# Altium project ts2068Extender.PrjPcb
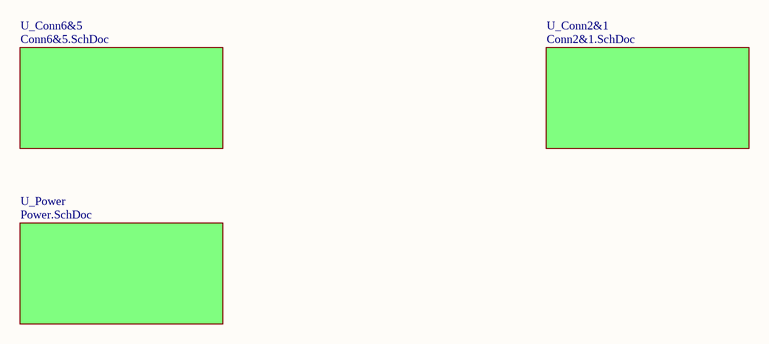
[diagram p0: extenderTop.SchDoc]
4 sheets, 15 parts. Net scope: global (net labels, ports and power ports of the same name join across sheets).
Sheets:
  extenderTop.SchDoc
    U_Power = Power.SchDoc
    U_Conn6&5 = Conn6&5.SchDoc
    U_Conn2&1 = Conn2&1.SchDoc

## Sheet extenderTop.SchDoc
size A

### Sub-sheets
U_Conn2&1 = Conn2&1.SchDoc: no entries
U_Conn6&5 = Conn6&5.SchDoc: no entries
U_Power = Power.SchDoc: no entries

## Sheet Power.SchDoc
size A
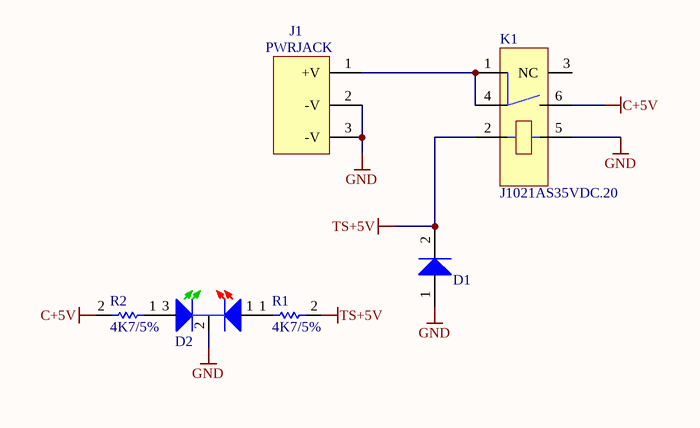
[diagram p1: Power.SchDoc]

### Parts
D1  1N4004  [DO41]  (value not drawn)
D2  XLMDKVG29M  [XLMDKVG29M]  (value not drawn)
J1  Comment_1: PWRJACK  [EJ503A]  (hidden comment: PWR2.1_5.5)
K1  J1021AS35VDC.20  [J1021AS]
R1  4K7/5%  [CF18]
R2  4K7/5%  [CF18]

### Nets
C+5V: K1.6 R2.2
GND: D1.1(A) D2.2(K) J1.2(-V) J1.3(-V) K1.5
TS+5V: D1.2(K) K1.2 R1.2
NetD2_1: D2.1(A) R1.1
NetD2_3: D2.3 R2.1
NetJ1_1: J1.1(+V) K1.1 K1.4

Not connected (* = marked no-connect by the designer): K1 3(NC)

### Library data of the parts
D1 = 1N4004: Diode 400 V 1A Through Hole DO-41; MFG PN: 1N4004-T; DK PN: N4004DICT-ND; MFG: Diodes Inc
D2 = XLMDKVG29M: 3MM BI-COLOR RED/GRN LED; DK PN: 1497-XLMDKVG29M-ND; MFG: Sun
J1 = PWR2.1_5.5: Power Barrel Connector Jack 2.10mm ID (0.083"), 5.50mm OD (0.217") Through Hole, Right Angle; DK PN: EJ503A-ND; MFG: Memory Protection Devices
K1 = J1021AS35VDC.20: RELAY GEN PURPOSE SPST 3A 5V; DK PN: 2449-J1021AS35VDC.20-ND; MFG: CIT
R1 R2 = 4K7/5%: RES 4.7K OHM 5% 1/8W AXIAL; MFG PN: CF18JT4K70; DK PN: CF18JT4K70CT-ND; MFG: Stackpole

## Sheet Conn6&5.SchDoc
size A
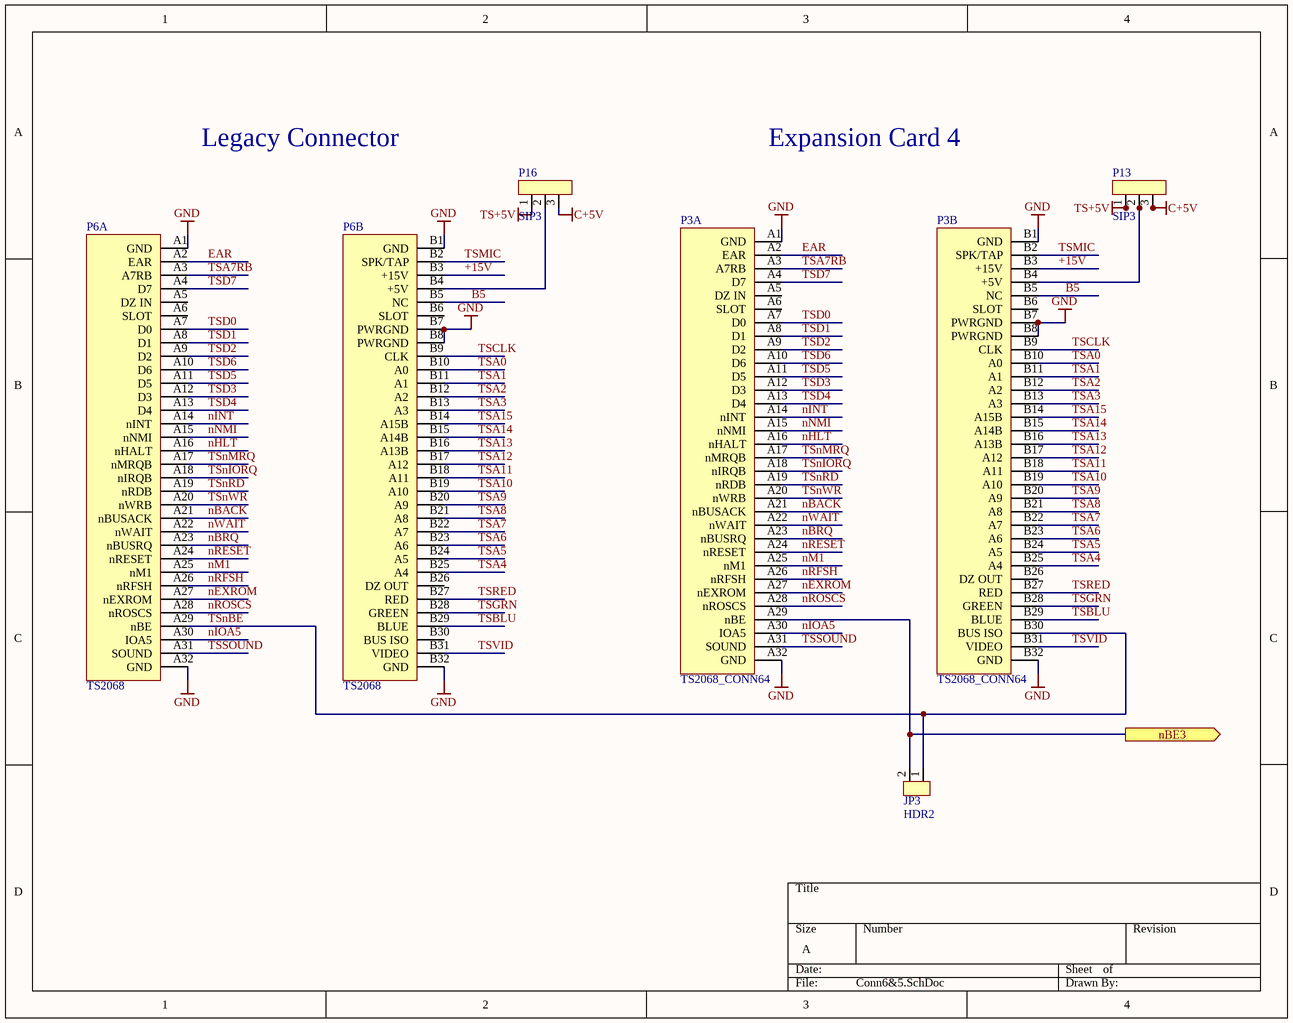
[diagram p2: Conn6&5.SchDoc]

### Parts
JP3  HDR2  [HDR2]
P3  TS2068_CONN64  [64CARDEDGE]  (parts A,B of 2)
P6  TS2068  [TS2068]  (parts A,B of 2)
P13  SIP3  [SIP3]
P16  SIP3  [SIP3]

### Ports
nBE3 (out)

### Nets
C+5V: P13.3 P16.3
GND: P3.A1(GND) P3.A32(GND) P3.B1(GND) P3.B7(PWRGND) P3.B8(PWRGND) P3.B32(GND) P6.A1(GND) P6.A32(GND) P6.B1(GND) P6.B7(PWRGND) P6.B8(PWRGND) P6.B32(GND)
TS+5V: P13.1 P16.1
+15V: P3.B3(+15V) P6.B3(+15V)
B5: P3.B5(NC) P6.B5(NC)
EAR: P3.A2(EAR) P6.A2(EAR)
nBACK: P3.A21(nBUSACK) P6.A21(nBUSACK)
nBE3: JP3.2 P3.A29(nBE) ; port nBE3
nBRQ: P3.A23(nBUSRQ) P6.A23(nBUSRQ)
nEXROM: P3.A27(nEXROM) P6.A27(nEXROM)
nHLT: P3.A16(nHALT) P6.A16(nHALT)
nINT: P3.A14(nINT) P6.A14(nINT)
nIOA5: P3.A30(IOA5) P6.A30(IOA5)
nM1: P3.A25(nM1) P6.A25(nM1)
nNMI: P3.A15(nNMI) P6.A15(nNMI)
nRESET: P3.A24(nRESET) P6.A24(nRESET)
nRFSH: P3.A26(nRFSH) P6.A26(nRFSH)
nROSCS: P3.A28(nROSCS) P6.A28(nROSCS)
nWAIT: P3.A22(nWAIT) P6.A22(nWAIT)
TSA0: P3.B10(A0) P6.B10(A0)
TSA1: P3.B11(A1) P6.B11(A1)
TSA2: P3.B12(A2) P6.B12(A2)
TSA3: P3.B13(A3) P6.B13(A3)
TSA4: P3.B25(A4) P6.B25(A4)
TSA5: P3.B24(A5) P6.B24(A5)
TSA6: P3.B23(A6) P6.B23(A6)
TSA7: P3.B22(A7) P6.B22(A7)
TSA7RB: P3.A3(A7RB) P6.A3(A7RB)
TSA8: P3.B21(A8) P6.B21(A8)
TSA9: P3.B20(A9) P6.B20(A9)
TSA10: P3.B19(A10) P6.B19(A10)
TSA11: P3.B18(A11) P6.B18(A11)
TSA12: P3.B17(A12) P6.B17(A12)
TSA13: P3.B16(A13B) P6.B16(A13B)
TSA14: P3.B15(A14B) P6.B15(A14B)
TSA15: P3.B14(A15B) P6.B14(A15B)
TSBLU: P3.B29(BLUE) P6.B29(BLUE)
TSCLK: P3.B9(CLK) P6.B9(CLK)
TSD0: P3.A7(D0) P6.A7(D0)
TSD1: P3.A8(D1) P6.A8(D1)
TSD2: P3.A9(D2) P6.A9(D2)
TSD3: P3.A12(D3) P6.A12(D3)
TSD4: P3.A13(D4) P6.A13(D4)
TSD5: P3.A11(D5) P6.A11(D5)
TSD6: P3.A10(D6) P6.A10(D6)
TSD7: P3.A4(D7) P6.A4(D7)
TSGRN: P3.B28(GREEN) P6.B28(GREEN)
TSMIC: P3.B2(SPK/TAP) P6.B2(SPK/TAP)
TSnBE: JP3.1 P3.B30(BUS_ISO) P6.A29(nBE)
TSnIORQ: P3.A18(nIRQB) P6.A18(nIRQB)
TSnMRQ: P3.A17(nMRQB) P6.A17(nMRQB)
TSnRD: P3.A19(nRDB) P6.A19(nRDB)
TSnWR: P3.A20(nWRB) P6.A20(nWRB)
TSRED: P3.B27(RED) P6.B27(RED)
TSSOUND: P3.A31(SOUND) P6.A31(SOUND)
TSVID: P3.B31(VIDEO) P6.B31(VIDEO)
NetP3_B4: P3.B4(+5V) P13.2
NetP6_B4: P6.B4(+5V) P16.2

Not connected (* = marked no-connect by the designer): P3 A5(DZ_IN) A6(SLOT) B6(SLOT) B26(DZ_OUT); P6 A5(DZ_IN) A6(SLOT) B6(SLOT) B26(DZ_OUT) B30(BUS_ISO)

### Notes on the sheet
- Legacy Connector
- Expansion Card 4

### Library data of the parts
P3 = TS2068_CONN64: 64 Position Female Connector Non Specified - Dual Edge Gold 0.100" (2.54mm) Black; MFG: TD; MFG PN: 1761469-1; DK PN: 1761469-1-ND

## Sheet Conn2&1.SchDoc
size A
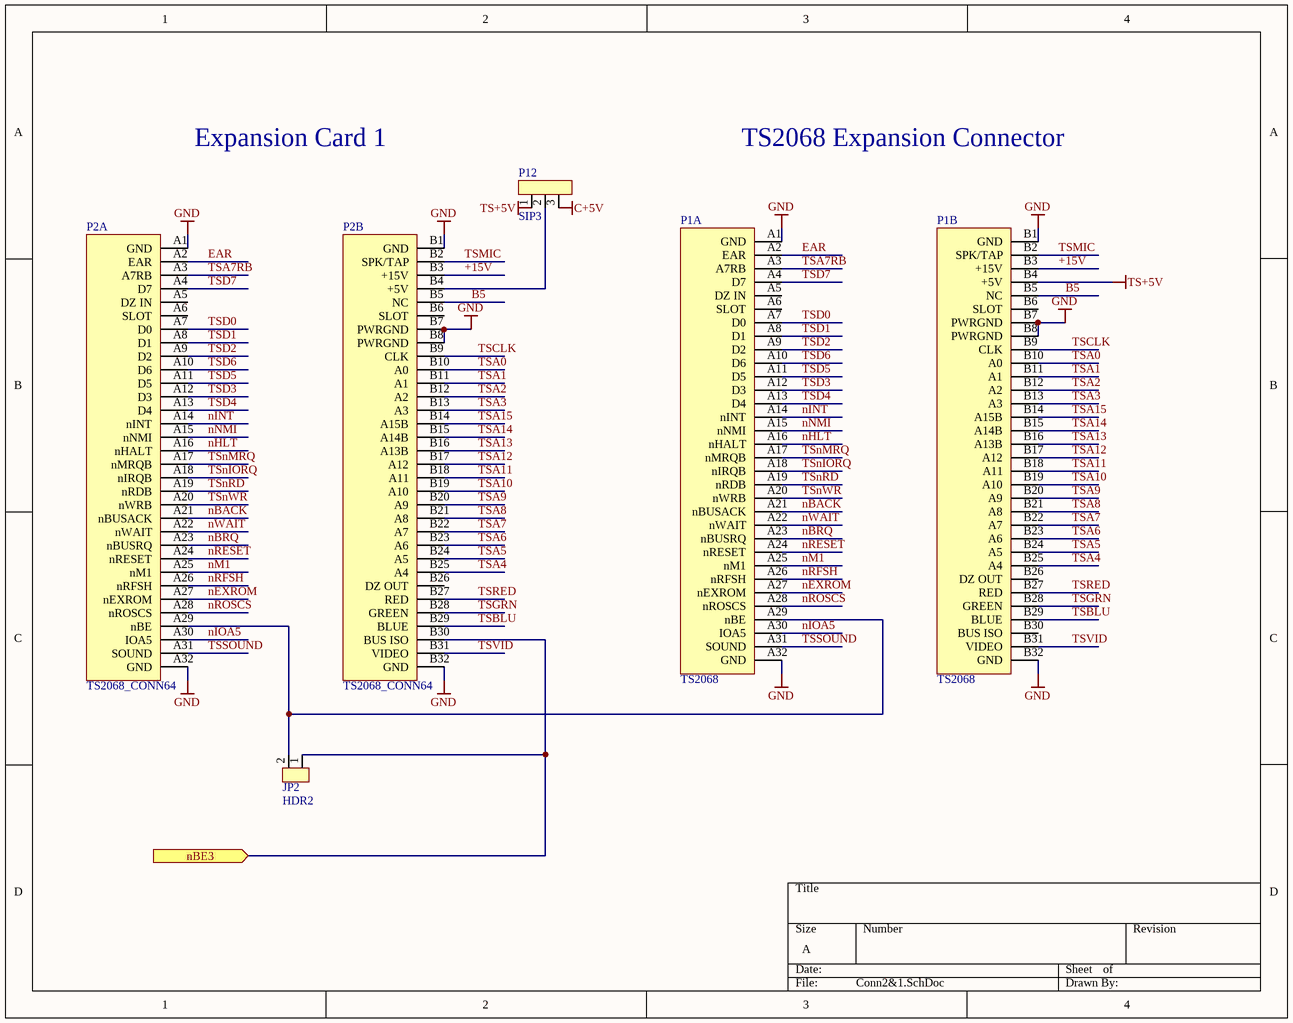
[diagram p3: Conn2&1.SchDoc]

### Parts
JP2  HDR2  [HDR2]
P1  TS2068  [TS2068]  (parts A,B of 2)
P2  TS2068_CONN64  [64CARDEDGE]  (parts A,B of 2)
P12  SIP3  [SIP3]

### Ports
nBE3 (in)

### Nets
C+5V: P12.3
GND: P1.A1(GND) P1.A32(GND) P1.B1(GND) P1.B7(PWRGND) P1.B8(PWRGND) P1.B32(GND) P2.A1(GND) P2.A32(GND) P2.B1(GND) P2.B7(PWRGND) P2.B8(PWRGND) P2.B32(GND)
TS+5V: P1.B4(+5V) P12.1
+15V: P1.B3(+15V) P2.B3(+15V)
B5: P1.B5(NC) P2.B5(NC)
EAR: P1.A2(EAR) P2.A2(EAR)
nBACK: P1.A21(nBUSACK) P2.A21(nBUSACK)
nBE3: JP2.1 P2.B30(BUS_ISO) ; port nBE3
nBRQ: P1.A23(nBUSRQ) P2.A23(nBUSRQ)
nEXROM: P1.A27(nEXROM) P2.A27(nEXROM)
nHLT: P1.A16(nHALT) P2.A16(nHALT)
nINT: P1.A14(nINT) P2.A14(nINT)
nIOA5: P1.A30(IOA5) P2.A30(IOA5)
nM1: P1.A25(nM1) P2.A25(nM1)
nNMI: P1.A15(nNMI) P2.A15(nNMI)
nRESET: P1.A24(nRESET) P2.A24(nRESET)
nRFSH: P1.A26(nRFSH) P2.A26(nRFSH)
nROSCS: P1.A28(nROSCS) P2.A28(nROSCS)
nWAIT: P1.A22(nWAIT) P2.A22(nWAIT)
TSA0: P1.B10(A0) P2.B10(A0)
TSA1: P1.B11(A1) P2.B11(A1)
TSA2: P1.B12(A2) P2.B12(A2)
TSA3: P1.B13(A3) P2.B13(A3)
TSA4: P1.B25(A4) P2.B25(A4)
TSA5: P1.B24(A5) P2.B24(A5)
TSA6: P1.B23(A6) P2.B23(A6)
TSA7: P1.B22(A7) P2.B22(A7)
TSA7RB: P1.A3(A7RB) P2.A3(A7RB)
TSA8: P1.B21(A8) P2.B21(A8)
TSA9: P1.B20(A9) P2.B20(A9)
TSA10: P1.B19(A10) P2.B19(A10)
TSA11: P1.B18(A11) P2.B18(A11)
TSA12: P1.B17(A12) P2.B17(A12)
TSA13: P1.B16(A13B) P2.B16(A13B)
TSA14: P1.B15(A14B) P2.B15(A14B)
TSA15: P1.B14(A15B) P2.B14(A15B)
TSBLU: P1.B29(BLUE) P2.B29(BLUE)
TSCLK: P1.B9(CLK) P2.B9(CLK)
TSD0: P1.A7(D0) P2.A7(D0)
TSD1: P1.A8(D1) P2.A8(D1)
TSD2: P1.A9(D2) P2.A9(D2)
TSD3: P1.A12(D3) P2.A12(D3)
TSD4: P1.A13(D4) P2.A13(D4)
TSD5: P1.A11(D5) P2.A11(D5)
TSD6: P1.A10(D6) P2.A10(D6)
TSD7: P1.A4(D7) P2.A4(D7)
TSGRN: P1.B28(GREEN) P2.B28(GREEN)
TSMIC: P1.B2(SPK/TAP) P2.B2(SPK/TAP)
TSnIORQ: P1.A18(nIRQB) P2.A18(nIRQB)
TSnMRQ: P1.A17(nMRQB) P2.A17(nMRQB)
TSnRD: P1.A19(nRDB) P2.A19(nRDB)
TSnWR: P1.A20(nWRB) P2.A20(nWRB)
TSRED: P1.B27(RED) P2.B27(RED)
TSSOUND: P1.A31(SOUND) P2.A31(SOUND)
TSVID: P1.B31(VIDEO) P2.B31(VIDEO)
NetJP2_2: JP2.2 P1.A29(nBE) P2.A29(nBE)
NetP2_B4: P2.B4(+5V) P12.2

Not connected (* = marked no-connect by the designer): P1 A5(DZ_IN) A6(SLOT) B6(SLOT) B26(DZ_OUT) B30(BUS_ISO); P2 A5(DZ_IN) A6(SLOT) B6(SLOT) B26(DZ_OUT)

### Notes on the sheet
- Expansion Card 1
- TS2068 Expansion Connector

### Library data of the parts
P2 = TS2068_CONN64: as P3 on sheet Conn6&5

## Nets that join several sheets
C+5V: Power (K1.6 R2.2), Conn6&5 (P13.3 P16.3), Conn2&1 (P12.3)
GND: Power (5 pins), Conn6&5 (12 pins), Conn2&1 (12 pins)
TS+5V: Power (D1.2 K1.2 R1.2), Conn6&5 (P13.1 P16.1), Conn2&1 (P1.B4 P12.1)
+15V: Conn6&5 (P3.B3 P6.B3), Conn2&1 (P1.B3 P2.B3)
B5: Conn6&5 (P3.B5 P6.B5), Conn2&1 (P1.B5 P2.B5)
EAR: Conn6&5 (P3.A2 P6.A2), Conn2&1 (P1.A2 P2.A2)
nBACK: Conn6&5 (P3.A21 P6.A21), Conn2&1 (P1.A21 P2.A21)
nBE3: Conn6&5 (JP3.2 P3.A29), Conn2&1 (JP2.1 P2.B30)
nBRQ: Conn6&5 (P3.A23 P6.A23), Conn2&1 (P1.A23 P2.A23)
nEXROM: Conn6&5 (P3.A27 P6.A27), Conn2&1 (P1.A27 P2.A27)
nHLT: Conn6&5 (P3.A16 P6.A16), Conn2&1 (P1.A16 P2.A16)
nINT: Conn6&5 (P3.A14 P6.A14), Conn2&1 (P1.A14 P2.A14)
nIOA5: Conn6&5 (P3.A30 P6.A30), Conn2&1 (P1.A30 P2.A30)
nM1: Conn6&5 (P3.A25 P6.A25), Conn2&1 (P1.A25 P2.A25)
nNMI: Conn6&5 (P3.A15 P6.A15), Conn2&1 (P1.A15 P2.A15)
nRESET: Conn6&5 (P3.A24 P6.A24), Conn2&1 (P1.A24 P2.A24)
nRFSH: Conn6&5 (P3.A26 P6.A26), Conn2&1 (P1.A26 P2.A26)
nROSCS: Conn6&5 (P3.A28 P6.A28), Conn2&1 (P1.A28 P2.A28)
nWAIT: Conn6&5 (P3.A22 P6.A22), Conn2&1 (P1.A22 P2.A22)
TSA0: Conn6&5 (P3.B10 P6.B10), Conn2&1 (P1.B10 P2.B10)
TSA1: Conn6&5 (P3.B11 P6.B11), Conn2&1 (P1.B11 P2.B11)
TSA2: Conn6&5 (P3.B12 P6.B12), Conn2&1 (P1.B12 P2.B12)
TSA3: Conn6&5 (P3.B13 P6.B13), Conn2&1 (P1.B13 P2.B13)
TSA4: Conn6&5 (P3.B25 P6.B25), Conn2&1 (P1.B25 P2.B25)
TSA5: Conn6&5 (P3.B24 P6.B24), Conn2&1 (P1.B24 P2.B24)
TSA6: Conn6&5 (P3.B23 P6.B23), Conn2&1 (P1.B23 P2.B23)
TSA7: Conn6&5 (P3.B22 P6.B22), Conn2&1 (P1.B22 P2.B22)
TSA7RB: Conn6&5 (P3.A3 P6.A3), Conn2&1 (P1.A3 P2.A3)
TSA8: Conn6&5 (P3.B21 P6.B21), Conn2&1 (P1.B21 P2.B21)
TSA9: Conn6&5 (P3.B20 P6.B20), Conn2&1 (P1.B20 P2.B20)
TSA10: Conn6&5 (P3.B19 P6.B19), Conn2&1 (P1.B19 P2.B19)
TSA11: Conn6&5 (P3.B18 P6.B18), Conn2&1 (P1.B18 P2.B18)
TSA12: Conn6&5 (P3.B17 P6.B17), Conn2&1 (P1.B17 P2.B17)
TSA13: Conn6&5 (P3.B16 P6.B16), Conn2&1 (P1.B16 P2.B16)
TSA14: Conn6&5 (P3.B15 P6.B15), Conn2&1 (P1.B15 P2.B15)
TSA15: Conn6&5 (P3.B14 P6.B14), Conn2&1 (P1.B14 P2.B14)
TSBLU: Conn6&5 (P3.B29 P6.B29), Conn2&1 (P1.B29 P2.B29)
TSCLK: Conn6&5 (P3.B9 P6.B9), Conn2&1 (P1.B9 P2.B9)
TSD0: Conn6&5 (P3.A7 P6.A7), Conn2&1 (P1.A7 P2.A7)
TSD1: Conn6&5 (P3.A8 P6.A8), Conn2&1 (P1.A8 P2.A8)
TSD2: Conn6&5 (P3.A9 P6.A9), Conn2&1 (P1.A9 P2.A9)
TSD3: Conn6&5 (P3.A12 P6.A12), Conn2&1 (P1.A12 P2.A12)
TSD4: Conn6&5 (P3.A13 P6.A13), Conn2&1 (P1.A13 P2.A13)
TSD5: Conn6&5 (P3.A11 P6.A11), Conn2&1 (P1.A11 P2.A11)
TSD6: Conn6&5 (P3.A10 P6.A10), Conn2&1 (P1.A10 P2.A10)
TSD7: Conn6&5 (P3.A4 P6.A4), Conn2&1 (P1.A4 P2.A4)
TSGRN: Conn6&5 (P3.B28 P6.B28), Conn2&1 (P1.B28 P2.B28)
TSMIC: Conn6&5 (P3.B2 P6.B2), Conn2&1 (P1.B2 P2.B2)
TSnIORQ: Conn6&5 (P3.A18 P6.A18), Conn2&1 (P1.A18 P2.A18)
TSnMRQ: Conn6&5 (P3.A17 P6.A17), Conn2&1 (P1.A17 P2.A17)
TSnRD: Conn6&5 (P3.A19 P6.A19), Conn2&1 (P1.A19 P2.A19)
TSnWR: Conn6&5 (P3.A20 P6.A20), Conn2&1 (P1.A20 P2.A20)
TSRED: Conn6&5 (P3.B27 P6.B27), Conn2&1 (P1.B27 P2.B27)
TSSOUND: Conn6&5 (P3.A31 P6.A31), Conn2&1 (P1.A31 P2.A31)
TSVID: Conn6&5 (P3.B31 P6.B31), Conn2&1 (P1.B31 P2.B31)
